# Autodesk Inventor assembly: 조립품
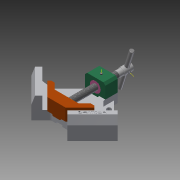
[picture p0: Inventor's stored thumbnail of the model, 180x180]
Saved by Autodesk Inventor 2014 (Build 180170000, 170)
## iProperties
Created: 2020-05
Part Number: 조립품
Document SubType Name: Assembly
Designer: kh
Author: kh
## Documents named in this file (11)
- C:\Users\kh\Desktop\700506V1027\조립품.iam
- C:\Users\kh\Desktop\700506V1027\베이스.ipt
- C:\Users\kh\Desktop\700506V1027\리드스크류.ipt
- C:\Users\kh\Desktop\700506V1027\멈춤나사 M4x5.ipt
- C:\Users\kh\Desktop\700506V1027\멈춤나사 M4x10.ipt
- C:\Users\kh\Desktop\700506V1027\볼트 M4x16.ipt
- C:\Users\kh\Desktop\700506V1027\부시.ipt
- C:\Users\kh\Desktop\700506V1027\서포트.ipt
- C:\Users\kh\Desktop\700506V1027\조.ipt
- C:\Users\kh\Desktop\700506V1027\평행 핀 2.5x24.ipt
- C:\Users\kh\Desktop\700506V1027\핸들.ipt
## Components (1 placed, 1 different names)
1. 핸들:1 — 각도:1
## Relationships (1: Angle 1)
- 각도:1 [Angle]: 핸들:1
